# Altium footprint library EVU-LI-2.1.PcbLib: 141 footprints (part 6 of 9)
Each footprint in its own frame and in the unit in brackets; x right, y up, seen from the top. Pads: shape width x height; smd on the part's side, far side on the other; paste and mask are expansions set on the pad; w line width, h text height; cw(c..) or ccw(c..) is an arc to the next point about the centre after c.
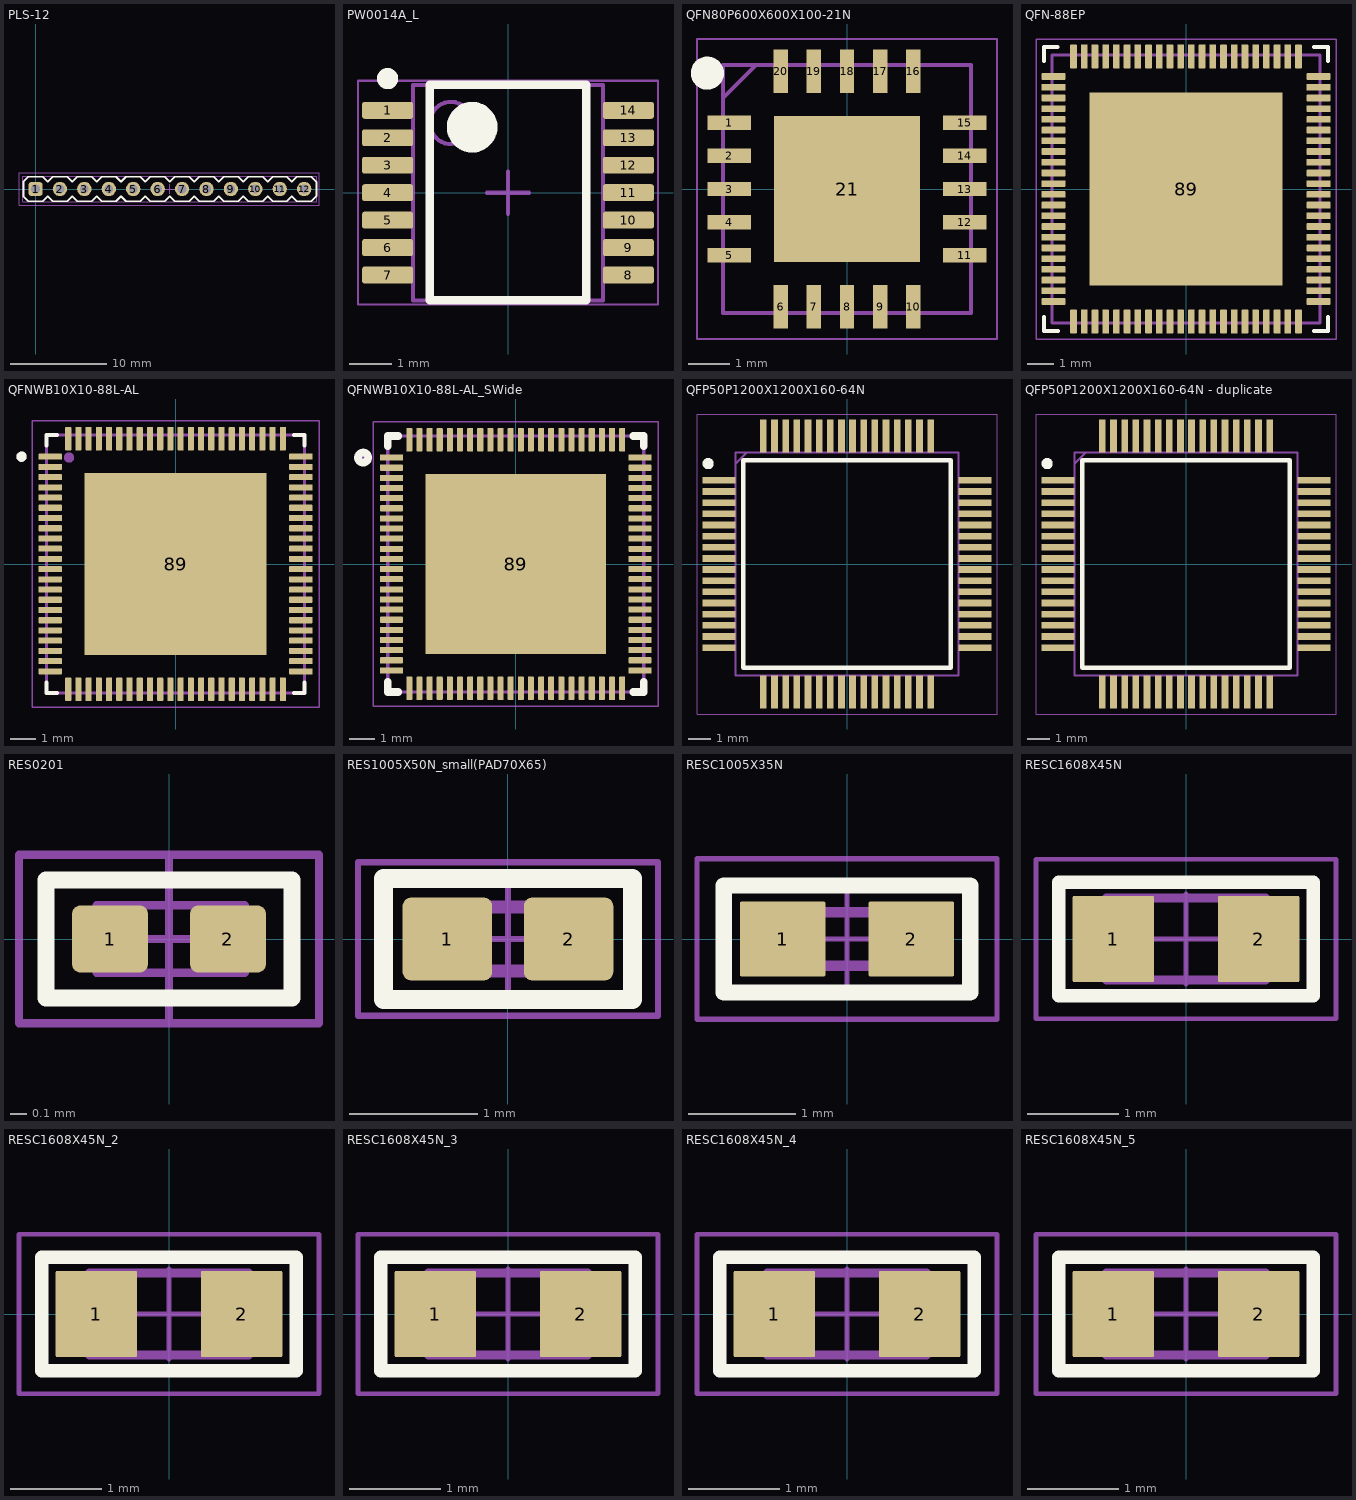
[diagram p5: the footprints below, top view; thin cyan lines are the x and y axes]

## PLS-12 [mm] "Pin Header, 2.54mm pitch"
height 8.5
pads (12):
  rrect50% 1.5x1.5 hole 0.9: 1(0,0)
  round 1.5 hole 0.9: 2(2.54,0) 3(5.08,0) 4(7.62,0) 5(10.16,0) 6(12.7,0) 7(15.24,0) 8(17.78,0) 9(20.32,0) 10(22.86,0) 11(25.4,0) 12(27.94,0)
Top Overlay:
  lines w0.2: -1.27,-0.75 -1.27,0.75 -0.75,1.27 0.75,1.27 1.27,0.75 1.79,1.27 3.29,1.27 3.81,0.75 4.33,1.27 5.83,1.27 6.35,0.75 6.87,1.27 8.37,1.27 8.89,0.75 9.41,1.27 10.91,1.27 11.43,0.75 11.95,1.27 13.45,1.27 13.97,0.75 14.49,1.27 15.99,1.27 16.51,0.75 17.03,1.27 18.53,1.27 19.05,0.75 19.57,1.27 21.07,1.27 21.59,0.75 22.11,1.27 23.61,1.27 24.13,0.75 24.65,1.27 26.15,1.27 26.67,0.75 27.19,1.27 28.69,1.27 29.21,0.75 29.21,-0.75 28.69,-1.27 27.19,-1.27 26.67,-0.75 26.15,-1.27 24.65,-1.27 24.13,-0.75 23.61,-1.27 22.11,-1.27 21.59,-0.75 21.07,-1.27 19.57,-1.27 19.05,-0.75 18.53,-1.27 17.03,-1.27 16.51,-0.75 15.99,-1.27 14.49,-1.27 13.97,-0.75 13.45,-1.27 11.95,-1.27 11.43,-0.75 10.91,-1.27 9.41,-1.27 8.89,-0.75 8.37,-1.27 6.87,-1.27 6.35,-0.75 5.83,-1.27 4.33,-1.27 3.81,-0.75 3.29,-1.27 1.79,-1.27 1.27,-0.75 0.75,-1.27 -0.75,-1.27 -1.27,-0.75
  text "." at -1.79,1.32 h6
Top Assembly:
  lines w0.1: -1.31,-1.31 29.26,-1.31 29.26,1.31 -1.31,1.31 -1.31,-1.31
  text ".Designator" at 11.196,0.231 h1.5
Top Value:
  text ".Comment" at 12.357,-0.858 h1
Top Courtyard:
  lines w0.05: 13.47,0 14.47,0 ; 13.97,-0.5 13.97,0.5 ; -1.717,-1.677 -1.717,1.677 29.48,1.677 29.48,-1.677 -1.717,-1.677
3D body "User Library-PLS-1.step": height 8.49, standoff -2.95, extent 26.67,-1.27 29.21,1.27
3D body "User Library-PLS-1.step": height 8.49, standoff -2.95, extent 24.13,-1.27 26.67,1.27
3D body "User Library-PLS-1.step": height 8.49, standoff -2.95, extent 21.59,-1.27 24.13,1.27
3D body "User Library-PLS-1.step": height 8.49, standoff -2.95, extent 19.05,-1.27 21.59,1.27
3D body "User Library-PLS-1.step": height 8.49, standoff -2.95, extent -1.27,-1.27 1.27,1.27
3D body "User Library-PLS-1.step": height 8.49, standoff -2.95, extent 1.27,-1.27 3.81,1.27
3D body "User Library-PLS-1.step": height 8.49, standoff -2.95, extent 3.81,-1.27 6.35,1.27
3D body "User Library-PLS-1.step": height 8.49, standoff -2.95, extent 6.35,-1.27 8.89,1.27
3D body "User Library-PLS-1.step": height 8.49, standoff -2.95, extent 8.89,-1.27 11.43,1.27
3D body "User Library-PLS-1.step": height 8.49, standoff -2.95, extent 11.43,-1.27 13.97,1.27
3D body "User Library-PLS-1.step": height 8.49, standoff -2.95, extent 13.97,-1.27 16.51,1.27
3D body "User Library-PLS-1.step": height 8.49, standoff -2.95, extent 16.51,-1.27 19.05,1.27

## PW0014A_L [mm] "SOP, 14-Leads, Body 5.1x4.5mm, Pitch 0.65mm, IPC High Density"
height 1.2
pads (14):
  rrect25% 1.2x0.4 smd: 1(-2.85,1.95) 2(-2.85,1.3) 3(-2.85,0.65) 4(-2.85,0) 5(-2.85,-0.65) 6(-2.85,-1.3) 7(-2.85,-1.95) 8(2.85,-1.95) 9(2.85,-1.3) 10(2.85,-0.65) 11(2.85,0) 12(2.85,0.65) 13(2.85,1.3) 14(2.85,1.95)
Top Overlay:
  circle w0.25: c-2.85,2.7 r0.125
  circle w0.6: c-0.85,1.55 r0.3
  lines w0.2: -1.85,-2.55 -1.85,2.55 1.85,2.55 1.85,-2.55 -1.85,-2.55
Mechanical 1:
  text ".Designator" at -1.524,-0.508 h1.02
Mechanical 13:
  circle w0.1: c-1.35,1.65 r0.5
  lines w0.1: -2.25,-2.55 -2.25,2.55 2.25,2.55 2.25,-2.55 -2.25,-2.55
Top Courtyard:
  lines w0.05: -3.55,-2.65 -3.55,2.65 3.55,2.65 3.55,-2.65 -3.55,-2.65
  lines w0.1: -0.5,0 0.5,0 ; 0,-0.5 0,0.5
3D body "PW0014AakaMTC14.stp": height 1, standoff 0, extent -3.21,-2.5 3.21,2.5

## QFN80P600X600X100-21N [mm]
pads (21):
  rect 1.05x0.35 smd: 1(-2.85,1.6) 2(-2.85,0.8) 3(-2.85,0) 4(-2.85,-0.8) 5(-2.85,-1.6) 11(2.85,-1.6) 12(2.85,-0.8) 13(2.85,0) 14(2.85,0.8) 15(2.85,1.6)
  rect 0.35x1.05 smd: 6(-1.6,-2.85) 7(-0.8,-2.85) 8(0,-2.85) 9(0.8,-2.85) 10(1.6,-2.85) 16(1.6,2.85) 17(0.8,2.85) 18(0,2.85) 19(-0.8,2.85) 20(-1.6,2.85)
  rect 3.53x3.53 smd: 21(0,0)
Top Overlay:
  circle w0.4: c-3.375,2.8 r0.2
Mechanical 13:
  lines w0.1: -3,2.2 -2.2,3 ; -3,-3 3,-3 3,3 -3,3 -3,-3
Top Courtyard:
  lines w0.05: -3.625,-3.625 3.625,-3.625 3.625,3.625 -3.625,3.625 -3.625,-3.625
3D body "ISL8560IRZ.stp": height 1, standoff 0, extent -3.05,-3.05 3.05,3.05

## QFN-88EP [mm] "10x10 EP 7x7"
height 0.9
pads (89):
  rrect25% 0.9x0.25 smd mask+0.05: 1(-4.95,4.2) 2(-4.95,3.8) 3(-4.95,3.4) 4(-4.95,3) 5(-4.95,2.6) 6(-4.95,2.2) 7(-4.95,1.8) 8(-4.95,1.4) 9(-4.95,1) 10(-4.95,0.6) 11(-4.95,0.2) 12(-4.95,-0.2) 13(-4.95,-0.6) 14(-4.95,-1) 15(-4.95,-1.4) 16(-4.95,-1.8) 17(-4.95,-2.2) 18(-4.95,-2.6) 19(-4.95,-3) 20(-4.95,-3.4) 21(-4.95,-3.8) 22(-4.95,-4.2) 45(4.95,-4.2) 46(4.95,-3.8) 47(4.95,-3.4) 48(4.95,-3) 49(4.95,-2.6) 50(4.95,-2.2) 51(4.95,-1.8) 52(4.95,-1.4) 53(4.95,-1) 54(4.95,-0.6) 55(4.95,-0.2) 56(4.95,0.2) 57(4.95,0.6) 58(4.95,1) 59(4.95,1.4) 60(4.95,1.8) 61(4.95,2.2) 62(4.95,2.6) 63(4.95,3) 64(4.95,3.4) 65(4.95,3.8) 66(4.95,4.2)
  rrect25% 0.25x0.9 smd mask+0.05: 23(-4.2,-4.95) 24(-3.8,-4.95) 25(-3.4,-4.95) 26(-3,-4.95) 27(-2.6,-4.95) 28(-2.2,-4.95) 29(-1.8,-4.95) 30(-1.4,-4.95) 31(-1,-4.95) 32(-0.6,-4.95) 33(-0.2,-4.95) 34(0.2,-4.95) 35(0.6,-4.95) 36(1,-4.95) 37(1.4,-4.95) 38(1.8,-4.95) 39(2.2,-4.95) 40(2.6,-4.95) 41(3,-4.95) 42(3.4,-4.95) 43(3.8,-4.95) 44(4.2,-4.95) 67(4.2,4.95) 68(3.8,4.95) 69(3.4,4.95) 70(3,4.95) 71(2.6,4.95) 72(2.2,4.95) 73(1.8,4.95) 74(1.4,4.95) 75(1,4.95) 76(0.6,4.95) 77(0.2,4.95) 78(-0.2,4.95) 79(-0.6,4.95) 80(-1,4.95) 81(-1.4,4.95) 82(-1.8,4.95) 83(-2.2,4.95) 84(-2.6,4.95) 85(-3,4.95) 86(-3.4,4.95) 87(-3.8,4.95) 88(-4.2,4.95)
  rect 7.2x7.2 smd paste-4.03 mask+0.075: 89(0,0)
Top Overlay:
  lines w0.15: -5.3,-4.774 -5.3,-5.3 -4.774,-5.3 ; -5.3,4.774 -5.3,5.3 -4.8,5.3 ; 4.774,-5.3 5.3,-5.3 5.3,-4.774 ; 4.774,5.3 5.3,5.3 5.3,4.774
  text "." at -5.4,5.5 h5
Top Paste:
  region: -1.5,1.1 -1.5,-1.1 -3.5,-1.1 -3.5,1.1
  region: 1.5,1.1 3.5,1.1 3.5,-1.1 1.5,-1.1
  region: -1.1,1.1 1.1,1.1 1.1,-1.1 -1.1,-1.1
  region: -1.1,-1.5 1.1,-1.5 1.1,-3.5 -1.1,-3.5
  region: 1.5,-1.5 3.5,-1.5 3.5,-3.5 1.5,-3.5
  region: -1.5,-1.5 -1.5,-3.5 -3.5,-3.5 -3.5,-1.5
  region: 3.5,1.5 1.5,1.5 1.5,3.5 3.5,3.5
  region: 1.1,1.5 -1.1,1.5 -1.1,3.5 1.1,3.5
  region: -1.5,1.5 -3.5,1.5 -3.5,3.5 -1.5,3.5
Top Assembly:
  lines w0.1: -5,-5 5,-5 5,5 -5,5 -5,-5
  text "." at -4.3,3.9 h6
  text ".Designator" at -2.814,0.061 h1.5
Top Value:
  text ".Comment" at -2.037,-1.39 h1.2
Top Courtyard:
  circle w0.05: c0,0 r0.25
  lines w0.05: -0.35,0 0.35,0 ; 0,-0.35 0,0.35 ; -5.6,-5.6 -5.6,5.6 5.6,5.6 5.6,-5.6 -5.6,-5.6
3D body "Baikal-U.STEP": height 0.9, standoff 0, extent -5,-5 5,5

## QFNWB10X10-88L-AL [mm]
pads (89):
  rrect25% 0.92x0.24 smd: 1(-4.905,4.2) 2(-4.905,3.8) 3(-4.905,3.4) 4(-4.905,3) 5(-4.905,2.6) 6(-4.905,2.2) 7(-4.905,1.8) 8(-4.905,1.4) 9(-4.905,1) 10(-4.905,0.6) 11(-4.905,0.2) 12(-4.905,-0.2) 13(-4.905,-0.6) 14(-4.905,-1) 15(-4.905,-1.4) 16(-4.905,-1.8) 17(-4.905,-2.2) 18(-4.905,-2.6) 19(-4.905,-3) 20(-4.905,-3.4) 21(-4.905,-3.8) 22(-4.905,-4.2) 45(4.905,-4.2) 46(4.905,-3.8) 47(4.905,-3.4) 48(4.905,-3) 49(4.905,-2.6) 50(4.905,-2.2) 51(4.905,-1.8) 52(4.905,-1.4) 53(4.905,-1) 54(4.905,-0.6) 55(4.905,-0.2) 56(4.905,0.2) 57(4.905,0.6) 58(4.905,1) 59(4.905,1.4) 60(4.905,1.8) 61(4.905,2.2) 62(4.905,2.6) 63(4.905,3) 64(4.905,3.4) 65(4.905,3.8) 66(4.905,4.2)
  rrect25% 0.24x0.92 smd: 23(-4.2,-4.905) 24(-3.8,-4.905) 25(-3.4,-4.905) 26(-3,-4.905) 27(-2.6,-4.905) 28(-2.2,-4.905) 29(-1.8,-4.905) 30(-1.4,-4.905) 31(-1,-4.905) 32(-0.6,-4.905) 33(-0.2,-4.905) 34(0.2,-4.905) 35(0.6,-4.905) 36(1,-4.905) 37(1.4,-4.905) 38(1.8,-4.905) 39(2.2,-4.905) 40(2.6,-4.905) 41(3,-4.905) 42(3.4,-4.905) 43(3.8,-4.905) 44(4.2,-4.905) 67(4.2,4.905) 68(3.8,4.905) 69(3.4,4.905) 70(3,4.905) 71(2.6,4.905) 72(2.2,4.905) 73(1.8,4.905) 74(1.4,4.905) 75(1,4.905) 76(0.6,4.905) 77(0.2,4.905) 78(-0.2,4.905) 79(-0.6,4.905) 80(-1,4.905) 81(-1.4,4.905) 82(-1.8,4.905) 83(-2.2,4.905) 84(-2.6,4.905) 85(-3,4.905) 86(-3.4,4.905) 87(-3.8,4.905) 88(-4.2,4.905)
  rect 7.112x7.112 smd paste-3: 89(0,0)
Top Overlay:
  circle w0.2: c-6.025,4.2 r0.1
  lines w0.15: -5.05,-4.64 -5.05,-5.05 -4.64,-5.05 ; -5.05,4.64 -5.05,5.05 -4.64,5.05 ; 4.64,-5.05 5.05,-5.05 5.05,-4.64 ; 4.64,5.05 5.05,5.05 5.05,4.64
Top Paste:
  region: -1.27,1.27 -1.27,-1.27 1.27,-1.27 1.27,1.27
  region: 1.53,1.27 1.53,-1.27 3.4,-1.27 3.4,1.27
  region: -3.4,1.27 -3.4,-1.27 -1.53,-1.27 -1.53,1.27
  region: -3.4,3.4 -3.4,1.53 -1.53,1.53 -1.53,3.4
  region: -1.27,3.4 -1.27,1.53 1.27,1.53 1.27,3.4
  region: 1.53,3.4 1.53,1.53 3.4,1.53 3.4,3.4
  region: 1.53,-1.53 1.53,-3.4 3.4,-3.4 3.4,-1.53
  region: -1.27,-1.53 -1.27,-3.4 1.27,-3.4 1.27,-1.53
  region: -3.4,-1.53 -3.4,-3.4 -1.53,-3.4 -1.53,-1.53
Top Assembly:
  circle w0.2: c-4.166,4.166 r0.1
  lines w0.1: -5.05,4.194 -5.05,4.2
  lines w0.127: -5.05,-5.05 5.05,-5.05 5.05,5.05 -5.05,5.05 -5.05,-5.05
Mechanical 13:
  circle w0.2: c-6.025,4.2 r0.1
  lines w0.127: -5.05,-5.05 5.05,-5.05 5.05,5.05 -5.05,5.05 -5.05,-5.05
Top Courtyard:
  lines w0.05: -5.615,-5.615 5.615,-5.615 5.615,5.615 -5.615,5.615 -5.615,-5.615
3D body "BE-U1000.STEP": height 0.85, standoff -0.03, extent -5.001,-5.001 5.001,5.001

## QFNWB10X10-88L-AL_SWide [mm]
pads (89):
  rrect25% 0.92x0.24 smd: 1(-4.905,4.2) 2(-4.905,3.8) 3(-4.905,3.4) 4(-4.905,3) 5(-4.905,2.6) 6(-4.905,2.2) 7(-4.905,1.8) 8(-4.905,1.4) 9(-4.905,1) 10(-4.905,0.6) 11(-4.905,0.2) 12(-4.905,-0.2) 13(-4.905,-0.6) 14(-4.905,-1) 15(-4.905,-1.4) 16(-4.905,-1.8) 17(-4.905,-2.2) 18(-4.905,-2.6) 19(-4.905,-3) 20(-4.905,-3.4) 21(-4.905,-3.8) 22(-4.905,-4.2) 45(4.905,-4.2) 46(4.905,-3.8) 47(4.905,-3.4) 48(4.905,-3) 49(4.905,-2.6) 50(4.905,-2.2) 51(4.905,-1.8) 52(4.905,-1.4) 53(4.905,-1) 54(4.905,-0.6) 55(4.905,-0.2) 56(4.905,0.2) 57(4.905,0.6) 58(4.905,1) 59(4.905,1.4) 60(4.905,1.8) 61(4.905,2.2) 62(4.905,2.6) 63(4.905,3) 64(4.905,3.4) 65(4.905,3.8) 66(4.905,4.2)
  rrect25% 0.24x0.92 smd: 23(-4.2,-4.905) 24(-3.8,-4.905) 25(-3.4,-4.905) 26(-3,-4.905) 27(-2.6,-4.905) 28(-2.2,-4.905) 29(-1.8,-4.905) 30(-1.4,-4.905) 31(-1,-4.905) 32(-0.6,-4.905) 33(-0.2,-4.905) 34(0.2,-4.905) 35(0.6,-4.905) 36(1,-4.905) 37(1.4,-4.905) 38(1.8,-4.905) 39(2.2,-4.905) 40(2.6,-4.905) 41(3,-4.905) 42(3.4,-4.905) 43(3.8,-4.905) 44(4.2,-4.905) 67(4.2,4.905) 68(3.8,4.905) 69(3.4,4.905) 70(3,4.905) 71(2.6,4.905) 72(2.2,4.905) 73(1.8,4.905) 74(1.4,4.905) 75(1,4.905) 76(0.6,4.905) 77(0.2,4.905) 78(-0.2,4.905) 79(-0.6,4.905) 80(-1,4.905) 81(-1.4,4.905) 82(-1.8,4.905) 83(-2.2,4.905) 84(-2.6,4.905) 85(-3,4.905) 86(-3.4,4.905) 87(-3.8,4.905) 88(-4.2,4.905)
  rect 7.112x7.112 smd paste-3: 89(0,0)
Top Overlay:
  circle w0.3: c-6.025,4.2 r0.2
  lines w0.3: -5.05,-4.64 -5.05,-5.05 -4.64,-5.05 ; -5.05,4.64 -5.05,5.05 -4.64,5.05 ; 4.64,-5.05 5.05,-5.05 5.05,-4.64 ; 4.64,5.05 5.05,5.05 5.05,4.64
Top Paste:
  region: -3.5,3.5 -3.5,1.53 -1.53,1.53 -1.53,3.5
  region: -1.27,3.5 -1.27,1.53 1.27,1.53 1.27,3.5
  region: 1.53,3.5 1.53,1.53 3.5,1.53 3.5,3.5
  region: -3.5,1.27 -3.5,-1.27 -1.53,-1.27 -1.53,1.27
  region: -3.5,-1.53 -3.5,-3.5 -1.53,-3.5 -1.53,-1.53
  region: -1.27,-1.53 -1.27,-3.5 1.27,-3.5 1.27,-1.53
  region: 1.53,-1.53 1.53,-3.5 3.5,-3.5 3.5,-1.53
  region: 1.53,1.27 1.53,-1.27 3.5,-1.27 3.5,1.27
  region: -1.27,1.27 -1.27,-1.27 1.27,-1.27 1.27,1.27
Mechanical 13:
  circle w0.2: c-6.025,4.2 r0.1
  lines w0.127: -5.05,-5.05 -5.05,5.05 5.05,5.05 5.05,-5.05 -5.05,-5.05
Top Courtyard:
  lines w0.05: -5.615,-5.615 -5.615,5.615 5.615,5.615 5.615,-5.615 -5.615,-5.615
3D body "CYUSB3312-88LTXI.STEP": height 1, standoff 0, extent -5,-5 5,5

## QFP50P1200X1200X160-64N [mm]
pads (64):
  rect 1.475x0.3 smd: 1(-5.738,3.75) 2(-5.738,3.25) 3(-5.738,2.75) 4(-5.738,2.25) 5(-5.738,1.75) 6(-5.738,1.25) 7(-5.738,0.75) 8(-5.738,0.25) 9(-5.738,-0.25) 10(-5.738,-0.75) 11(-5.738,-1.25) 12(-5.738,-1.75) 13(-5.738,-2.25) 14(-5.738,-2.75) 15(-5.738,-3.25) 16(-5.738,-3.75) 33(5.738,-3.75) 34(5.738,-3.25) 35(5.738,-2.75) 36(5.738,-2.25) 37(5.738,-1.75) 38(5.738,-1.25) 39(5.738,-0.75) 40(5.738,-0.25) 41(5.738,0.25) 42(5.738,0.75) 43(5.738,1.25) 44(5.738,1.75) 45(5.738,2.25) 46(5.738,2.75) 47(5.738,3.25) 48(5.738,3.75)
  rect 0.3x1.475 smd: 17(-3.75,-5.738) 18(-3.25,-5.738) 19(-2.75,-5.738) 20(-2.25,-5.738) 21(-1.75,-5.738) 22(-1.25,-5.738) 23(-0.75,-5.738) 24(-0.25,-5.738) 25(0.25,-5.738) 26(0.75,-5.738) 27(1.25,-5.738) 28(1.75,-5.738) 29(2.25,-5.738) 30(2.75,-5.738) 31(3.25,-5.738) 32(3.75,-5.738) 49(3.75,5.738) 50(3.25,5.738) 51(2.75,5.738) 52(2.25,5.738) 53(1.75,5.738) 54(1.25,5.738) 55(0.75,5.738) 56(0.25,5.738) 57(-0.25,5.738) 58(-0.75,5.738) 59(-1.25,5.738) 60(-1.75,5.738) 61(-2.25,5.738) 62(-2.75,5.738) 63(-3.25,5.738) 64(-3.75,5.738)
Top Overlay:
  circle w0.25: c-6.225,4.5 r0.125
  lines w0.2: -4.65,-4.65 4.65,-4.65 4.65,4.65 -4.65,4.65 -4.65,-4.65
Mechanical 13:
  lines w0.1: -5,4.5 -4.5,5 ; -5,-5 5,-5 5,5 -5,5 -5,-5
Top Courtyard:
  lines w0.05: -6.725,-6.725 6.725,-6.725 6.725,6.725 -6.725,6.725 -6.725,-6.725
3D body "FT2232HL-REEL.stp": height 1.6, standoff 0, extent -6,-6 6,6

## QFP50P1200X1200X160-64N - duplicate [mm]
pads (64):
  rect 1.475x0.3 smd: 1(-5.738,3.75) 2(-5.738,3.25) 3(-5.738,2.75) 4(-5.738,2.25) 5(-5.738,1.75) 6(-5.738,1.25) 7(-5.738,0.75) 8(-5.738,0.25) 9(-5.738,-0.25) 10(-5.738,-0.75) 11(-5.738,-1.25) 12(-5.738,-1.75) 13(-5.738,-2.25) 14(-5.738,-2.75) 15(-5.738,-3.25) 16(-5.738,-3.75) 33(5.738,-3.75) 34(5.738,-3.25) 35(5.738,-2.75) 36(5.738,-2.25) 37(5.738,-1.75) 38(5.738,-1.25) 39(5.738,-0.75) 40(5.738,-0.25) 41(5.738,0.25) 42(5.738,0.75) 43(5.738,1.25) 44(5.738,1.75) 45(5.738,2.25) 46(5.738,2.75) 47(5.738,3.25) 48(5.738,3.75)
  rect 0.3x1.475 smd: 17(-3.75,-5.738) 18(-3.25,-5.738) 19(-2.75,-5.738) 20(-2.25,-5.738) 21(-1.75,-5.738) 22(-1.25,-5.738) 23(-0.75,-5.738) 24(-0.25,-5.738) 25(0.25,-5.738) 26(0.75,-5.738) 27(1.25,-5.738) 28(1.75,-5.738) 29(2.25,-5.738) 30(2.75,-5.738) 31(3.25,-5.738) 32(3.75,-5.738) 49(3.75,5.738) 50(3.25,5.738) 51(2.75,5.738) 52(2.25,5.738) 53(1.75,5.738) 54(1.25,5.738) 55(0.75,5.738) 56(0.25,5.738) 57(-0.25,5.738) 58(-0.75,5.738) 59(-1.25,5.738) 60(-1.75,5.738) 61(-2.25,5.738) 62(-2.75,5.738) 63(-3.25,5.738) 64(-3.75,5.738)
Top Overlay:
  circle w0.25: c-6.225,4.5 r0.125
  lines w0.2: -4.65,-4.65 4.65,-4.65 4.65,4.65 -4.65,4.65 -4.65,-4.65
Mechanical 13:
  lines w0.1: -5,4.5 -4.5,5 ; -5,-5 5,-5 5,5 -5,5 -5,-5
Top Courtyard:
  lines w0.05: -6.725,-6.725 6.725,-6.725 6.725,6.725 -6.725,6.725 -6.725,-6.725
3D body "FT2232HL-REEL.stp": height 1.6, standoff 0, extent -6,-6 6,6

## RES0201 [mm] "SMD Chip Resistor 0201,  metric 0603"
height 0.33
pads (2):
  rrect25% 0.45x0.4 smd mask+0.075: 1(-0.35,0) 2(0.35,0)
Top Overlay:
  lines w0.1: -0.73,-0.35 0.73,-0.35 0.73,0.35 -0.73,0.35 -0.73,-0.35
Top Assembly:
  lines w0.05: -0.43,-0.2 -0.43,0.2 0.45,0.2 0.45,-0.2 -0.43,-0.2
  text ".Designator" at -0.844,-0.087 h0.45
Top Value:
  text ".Comment" at -0.611,-0.35 h0.3
Top Courtyard:
  lines w0.05: -0.5,0 0.5,0 ; 0,-0.5 0,0.5 ; -0.89,-0.5 0.89,-0.5 0.89,0.5 -0.89,0.5 -0.89,-0.5
3D body "SMD_RESISTOR_0201.step": height 0.34, standoff 0, extent -0.34,-0.165 0.34,0.165

## RES1005X50N_small(PAD70X65) [mm]
pads (2):
  rrect20% 0.7x0.65 smd paste-25.4 mask+0.07: 1(-0.475,0) 2(0.475,0)
Top Overlay:
  lines w0.15: -0.975,-0.475 -0.975,0.475 0.975,0.475 0.975,-0.475 -0.975,-0.475
Top Paste:
  region: 0.234,-0.241 0.716,-0.241 0.716,0.241 0.234,0.241
  region: -0.234,-0.241 -0.716,-0.241 -0.716,0.241 -0.234,0.241
Top Assembly:
  lines w0.1: -0.508,-0.25 -0.508,0.25 0.492,0.25 0.492,-0.25 -0.508,-0.25
Top Designator:
  text ".Designator" at -3.375,-0.325 h1.5
Mechanical 9:
  text ".MARK" at -1.778,-0.354 h1.2
Top Courtyard:
  lines w0.05: -0.5,0 0.5,0 ; 0,-0.5 0,0.5 ; -1.175,-0.6 -1.175,0.6 1.175,0.6 1.175,-0.6 -1.175,-0.6
3D body "0402r.STEP": height 0.4, standoff 0, extent -0.575,-0.275 0.575,0.275

## RESC1005X35N [mm]
pads (2):
  rrect5% 0.8x0.7 smd paste-25.4 mask+0.07: 1(-0.6,0) 2(0.6,0)
Top Overlay:
  lines w0.15: -1.15,-0.5 1.15,-0.5 1.15,0.5 -1.15,0.5 -1.15,-0.5
Top Paste:
  region: 0.359,-0.241 0.841,-0.241 0.841,0.241 0.359,0.241
  region: -0.841,-0.241 -0.359,-0.241 -0.359,0.241 -0.841,0.241
Top Assembly:
  lines w0.1: -0.508,-0.25 0.492,-0.25 0.492,0.25 -0.508,0.25 -0.508,-0.25
Top Designator:
  text ".Designator" at -3.375,-0.3 h1.5
Mechanical 9:
  text ".MARK" at -1.651,-0.381 h1.2
Top Courtyard:
  lines w0.05: -0.5,0 0.5,0 ; 0,-0.5 0,0.5 ; -1.4,-0.75 1.4,-0.75 1.4,0.75 -1.4,0.75 -1.4,-0.75
3D body "RESC1005X04N.step": height 0.4, standoff 0, extent -0.55,-0.275 0.55,0.275

## RESC1608X45N [mm]
pads (2):
  rrect5% 0.9x0.95 smd mask+0.07: 1(-0.8,0) 2(0.8,0)
Top Overlay:
  lines w0.15: -1.4,-0.625 1.4,-0.625 1.4,0.625 -1.4,0.625 -1.4,-0.625
Top Assembly:
  lines w0.1: -0.875,-0.45 -0.875,0.45 0.875,0.45 0.875,-0.45 -0.875,-0.45
Top Designator:
  text ".Designator" at -3.25,-0.3 h1.5
Mechanical 9:
  text ".MARK" at -1.725,-0.341 h1.2
Top Courtyard:
  lines w0.05: -0.5,0 0.5,0 ; 0,-0.5 0,0.5 ; -1.65,-0.875 -1.65,0.875 1.65,0.875 1.65,-0.875 -1.65,-0.875
3D body "RESC1608X06N.step": height 0.55, standoff 0, extent -0.85,-0.45 0.85,0.45

## RESC1608X45N_2 [mm]
pads (2):
  rrect5% 0.9x0.95 smd mask+0.07: 1(-0.8,0) 2(0.8,0)
Top Overlay:
  lines w0.15: -1.4,-0.625 1.4,-0.625 1.4,0.625 -1.4,0.625 -1.4,-0.625
Top Assembly:
  lines w0.1: -0.875,-0.45 -0.875,0.45 0.875,0.45 0.875,-0.45 -0.875,-0.45
Top Designator:
  text ".Designator" at -3.25,-0.3 h1.5
Mechanical 9:
  text ".MARK" at -1.725,-0.341 h1.2
Top Courtyard:
  lines w0.05: -0.5,0 0.5,0 ; 0,-0.5 0,0.5 ; -1.65,-0.875 -1.65,0.875 1.65,0.875 1.65,-0.875 -1.65,-0.875
3D body "RESC1608X06N.step": height 0.55, standoff 0, extent -0.85,-0.45 0.85,0.45

## RESC1608X45N_3 [mm]
pads (2):
  rrect5% 0.9x0.95 smd mask+0.07: 1(-0.8,0) 2(0.8,0)
Top Overlay:
  lines w0.15: -1.4,-0.625 1.4,-0.625 1.4,0.625 -1.4,0.625 -1.4,-0.625
Top Assembly:
  lines w0.1: -0.875,-0.45 -0.875,0.45 0.875,0.45 0.875,-0.45 -0.875,-0.45
Top Designator:
  text ".Designator" at -3.25,-0.3 h1.5
Mechanical 9:
  text ".MARK" at -1.725,-0.341 h1.2
Top Courtyard:
  lines w0.05: -0.5,0 0.5,0 ; 0,-0.5 0,0.5 ; -1.65,-0.875 -1.65,0.875 1.65,0.875 1.65,-0.875 -1.65,-0.875
3D body "RESC1608X06N.step": height 0.55, standoff 0, extent -0.85,-0.45 0.85,0.45

## RESC1608X45N_4 [mm]
pads (2):
  rrect5% 0.9x0.95 smd mask+0.07: 1(-0.8,0) 2(0.8,0)
Top Overlay:
  lines w0.15: -1.4,-0.625 1.4,-0.625 1.4,0.625 -1.4,0.625 -1.4,-0.625
Top Assembly:
  lines w0.1: -0.875,-0.45 -0.875,0.45 0.875,0.45 0.875,-0.45 -0.875,-0.45
Top Designator:
  text ".Designator" at -3.25,-0.3 h1.5
Mechanical 9:
  text ".MARK" at -1.725,-0.341 h1.2
Top Courtyard:
  lines w0.05: -0.5,0 0.5,0 ; 0,-0.5 0,0.5 ; -1.65,-0.875 -1.65,0.875 1.65,0.875 1.65,-0.875 -1.65,-0.875
3D body "RESC1608X06N.step": height 0.55, standoff 0, extent -0.85,-0.45 0.85,0.45

## RESC1608X45N_5 [mm]
pads (2):
  rrect5% 0.9x0.95 smd mask+0.07: 1(-0.8,0) 2(0.8,0)
Top Overlay:
  lines w0.15: -1.4,-0.625 -1.4,0.625 1.4,0.625 1.4,-0.625 -1.4,-0.625
Top Assembly:
  lines w0.1: -0.875,-0.45 0.875,-0.45 0.875,0.45 -0.875,0.45 -0.875,-0.45
Top Designator:
  text ".Designator" at -1,-0.5 h1.5
Mechanical 9:
  text ".MARK" at -1.725,-0.341 h1.2
Top Courtyard:
  lines w0.05: -0.5,0 0.5,0 ; 0,-0.5 0,0.5 ; -1.65,-0.875 1.65,-0.875 1.65,0.875 -1.65,0.875 -1.65,-0.875
3D body "RESC1608X06N.step": height 0.55, standoff 0, extent -0.85,-0.45 0.85,0.45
